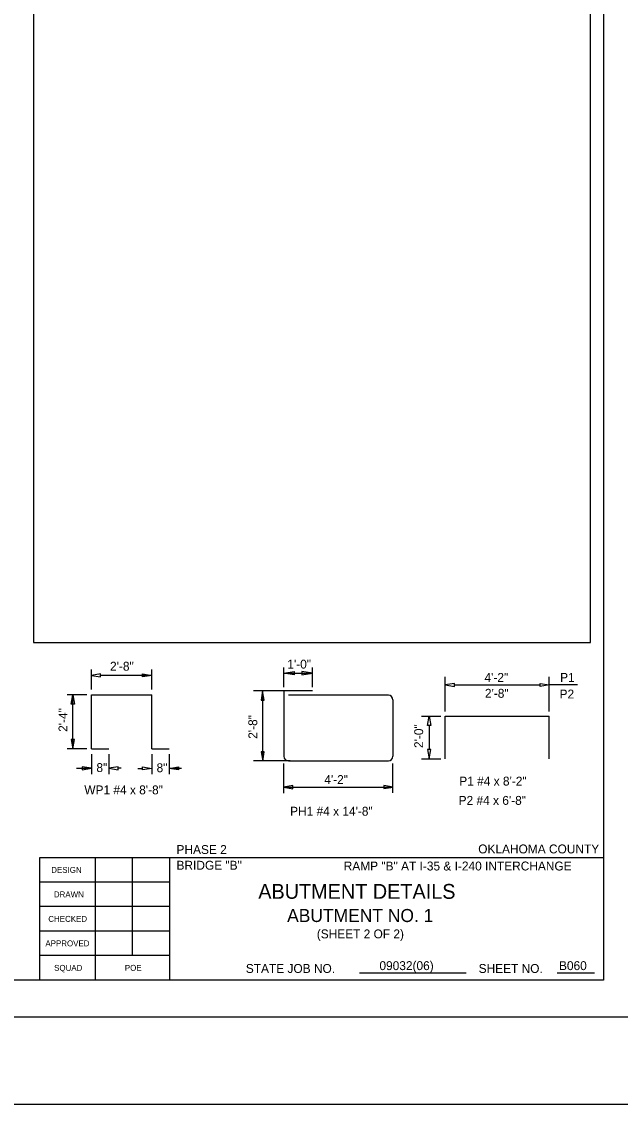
# Model space of a CAD drawing. Extents: x 2146724 to 2153191, y 139029 to 143935.
# Drawn here: x 2147223.9 to 2147256.2, y 143589.8 to 143648.2 of the extents above; entities that cross this region are included whole.
import ezdxf

# ---------------------------------------------------------------- set-up
doc = ezdxf.new("R2010")
doc.units = 0
for name, color, linetype in [('Default', 7, 'Continuous'), ('PR_Bridge_Rebar', 7, 'Continuous'), ('PR_Dimensions', 7, 'Continuous'), ('SHT_Plot_Shape_Full', 7, 'Continuous'), ('SHT_Plot_Shape_Half', 7, 'Continuous'), ('SHT_Sheet_Border', 7, 'Continuous'), ('SHT_Standard_Sheet_Lines', 7, 'Continuous'), ('SHT_Standard_Sheet_Txt', 7, 'Continuous'), ('T', 7, 'Continuous'), ('T-Subtitle', 7, 'Continuous'), ('T-Title', 7, 'Continuous')]:
    doc.layers.add(name, color=color, linetype=linetype)

# ---------------------------------------------------------------- blocks, each defined once
blk = doc.blocks.new('ARROWHD_11')
at = {"layer": 'Default'}
blk.add_lwpolyline([(0.0261, -0.0045), (0.0261, 0.0043), (-0.0004, -0.0001)], close=True, dxfattribs=at)

msp = doc.modelspace()

# ---------------------------------------------------------------- linework, layer by layer
at = {"layer": 'PR_Bridge_Rebar'}
for p, q in [((2147227.664, 143611.849), (2147230.921, 143611.849)), ((2147227.664, 143608.951), (2147227.664, 143611.849)), ((2147230.921, 143608.951), (2147230.921, 143611.849)), ((2147238.049, 143612.068), (2147238.049, 143608.543)), ((2147239.588, 143612.068), (2147238.049, 143612.068)), ((2147243.687, 143611.833), (2147238.299, 143611.833)), ((2147243.937, 143611.583), (2147243.937, 143608.543)), ((2147246.749, 143610.708), (2147252.37, 143610.708)), ((2147246.749, 143608.411), (2147246.749, 143610.708)), ((2147252.37, 143608.411), (2147252.37, 143610.708)), ((2147227.664, 143608.951), (2147228.606, 143608.951)), ((2147230.921, 143608.951), (2147231.863, 143608.951)), ((2147238.299, 143608.293), (2147243.687, 143608.293))]:
    msp.add_line(p, q, dxfattribs=at)
for centre, start, end in [((2147243.687, 143611.583), 0, 90), ((2147238.299, 143608.543), 180, 270), ((2147243.687, 143608.543), 270, 0)]:
    msp.add_arc(centre, 0.25, start, end, dxfattribs=at)
at = {"layer": 'PR_Dimensions'}
for p, q in [((2147227.664, 143612.141), (2147227.664, 143613.22)), ((2147230.921, 143612.906), (2147228.164, 143612.906)), ((2147230.921, 143612.141), (2147230.921, 143613.22)), ((2147238.049, 143612.266), (2147238.049, 143613.323)), ((2147238.049, 143613.024), (2147239.588, 143613.024)), ((2147239.588, 143612.266), (2147239.588, 143613.323)), ((2147246.749, 143610.958), (2147246.749, 143612.836)), ((2147252.37, 143610.958), (2147252.37, 143612.836)), ((2147247.249, 143612.39), (2147251.87, 143612.39)), ((2147253.892, 143612.39), (2147252.37, 143612.39)), ((2147227.414, 143611.849), (2147226.354, 143611.849)), ((2147226.665, 143608.951), (2147226.665, 143611.849)), ((2147238.412, 143612.068), (2147236.417, 143612.068)), ((2147236.906, 143612.068), (2147236.906, 143608.293)), ((2147245.478, 143610.708), (2147246.513, 143610.708)), ((2147245.892, 143610.208), (2147245.892, 143608.911)), ((2147227.414, 143608.951), (2147226.354, 143608.951)), ((2147227.664, 143608.658), (2147227.664, 143607.583)), ((2147228.606, 143608.658), (2147228.606, 143607.583)), ((2147230.921, 143608.658), (2147230.921, 143607.576)), ((2147231.863, 143608.658), (2147231.863, 143607.576)), ((2147238.381, 143608.293), (2147236.417, 143608.293)), ((2147245.478, 143608.411), (2147246.513, 143608.411)), ((2147226.868, 143607.897), (2147227.664, 143607.897)), ((2147229.276, 143607.897), (2147229.106, 143607.897)), ((2147230.169, 143607.889), (2147230.421, 143607.889)), ((2147232.527, 143607.889), (2147231.863, 143607.889)), ((2147238.049, 143606.56), (2147238.049, 143608.16)), ((2147243.937, 143606.569), (2147243.937, 143608.16)), ((2147238.049, 143606.883), (2147243.937, 143606.883))]:
    msp.add_line(p, q, dxfattribs=at)
for points in [[(2147224.535, 143614.674), (2147254.586, 143614.674), (2147254.586, 143656.446), (2147224.535, 143656.446)], [(2147228.164, 143612.823), (2147228.164, 143612.99), (2147227.664, 143612.906)], [(2147230.421, 143612.823), (2147230.421, 143612.99), (2147230.921, 143612.906)], [(2147238.609, 143612.931), (2147238.049, 143613.024), (2147238.609, 143613.117)], [(2147239.028, 143612.931), (2147239.588, 143613.024), (2147239.028, 143613.117)], [(2147247.249, 143612.306), (2147247.249, 143612.473), (2147246.749, 143612.39)], [(2147251.87, 143612.306), (2147251.87, 143612.473), (2147252.37, 143612.39)], [(2147226.749, 143611.349), (2147226.582, 143611.349), (2147226.665, 143611.849)], [(2147245.975, 143610.208), (2147245.808, 143610.208), (2147245.892, 143610.708)], [(2147226.747, 143609.444), (2147226.58, 143609.444), (2147226.664, 143608.944)], [(2147245.975, 143608.911), (2147245.808, 143608.911), (2147245.892, 143608.411)], [(2147227.164, 143607.98), (2147227.164, 143607.814), (2147227.664, 143607.897)], [(2147229.106, 143607.814), (2147229.106, 143607.98), (2147228.606, 143607.897)], [(2147230.421, 143607.806), (2147230.421, 143607.973), (2147230.921, 143607.889)], [(2147232.363, 143607.973), (2147232.363, 143607.806), (2147231.863, 143607.889)]]:
    msp.add_lwpolyline(points, close=True, dxfattribs=at)
at = {"layer": 'SHT_Plot_Shape_Full'}
msp.add_lwpolyline([(2147114.94, 143685.779), (2147258.94, 143685.779), (2147258.94, 143589.779), (2147114.94, 143589.779)], close=True, dxfattribs=at)
at = {"layer": 'SHT_Plot_Shape_Half'}
msp.add_lwpolyline([(2147121.49, 143682.479), (2147257.49, 143682.479), (2147257.49, 143594.479), (2147121.49, 143594.479)], close=True, dxfattribs=at)
at = {"layer": 'SHT_Sheet_Border'}
for p, q in [((2147224.89, 143596.479), (2147224.89, 143603.079)), ((2147224.89, 143603.079), (2147255.29, 143603.079)), ((2147231.889, 143596.479), (2147231.889, 143603.082)), ((2147231.889, 143596.479), (2147231.889, 143603.082))]:
    msp.add_line(p, q, dxfattribs=at)
msp.add_lwpolyline([(2147255.29, 143596.479), (2147129.29, 143596.479), (2147129.29, 143680.479), (2147255.29, 143680.479)], close=True, dxfattribs=at)
at = {"layer": 'SHT_Standard_Sheet_Lines'}
for p, q in [((2147227.889, 143596.479), (2147227.889, 143603.082)), ((2147229.889, 143597.8), (2147229.889, 143603.082)), ((2147242.132, 143596.864), (2147247.894, 143596.864)), ((2147242.132, 143596.864), (2147247.894, 143596.864)), ((2147252.791, 143596.864), (2147254.801, 143596.864)), ((2147252.791, 143596.864), (2147254.801, 143596.864))]:
    msp.add_line(p, q, dxfattribs=at)
for points in [[(2147231.889, 143601.759), (2147224.89, 143601.759)], [(2147231.889, 143600.439), (2147224.89, 143600.439)], [(2147231.889, 143599.119), (2147224.89, 143599.119)], [(2147231.889, 143597.799), (2147224.89, 143597.799)]]:
    msp.add_lwpolyline(points, dxfattribs=at)

# ---------------------------------------------------------------- block references
at = {"layer": 'PR_Dimensions', "xscale": 18.897599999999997, "yscale": 18.897599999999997}
for p, rotation in [((2147236.906, 143612.068), -90.00000000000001), ((2147236.906, 143608.293), 89.99999999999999), ((2147243.937, 143606.883), 180)]:
    msp.add_blockref('ARROWHD_11', p, dxfattribs=dict(at, rotation=rotation))
msp.add_blockref('ARROWHD_11', (2147238.049, 143606.883), dxfattribs=at)

# ---------------------------------------------------------------- texts
at = {"layer": 'SHT_Standard_Sheet_Txt'}
for s, height, p in [('DESIGN', 0.32, (2147225.498, 143602.259)), ('DRAWN', 0.32, (2147225.641, 143600.938)), ('CHECKED', 0.32, (2147225.341, 143599.618)), ('APPROVED', 0.32, (2147225.184, 143598.297)), ('SQUAD', 0.32, (2147225.655, 143596.976)), ('POE', 0.32, (2147229.47, 143596.979)), ('STATE JOB NO.', 0.48, (2147235.998, 143596.864)), ('STATE JOB NO.', 0.48, (2147235.998, 143596.864)), ('SHEET NO. ', 0.48, (2147248.558, 143596.864)), ('SHEET NO. ', 0.48, (2147248.559, 143596.864))]:
    msp.add_text(s, height=height, dxfattribs=at).set_placement(p)
at = {"layer": 'T'}
for s, height, p in [('2\'-8"', 0.48, (2147228.672, 143613.159)), ('1\'-0"', 0.48, (2147238.238, 143613.273)), ('4\'-2"', 0.48, (2147248.877, 143612.557)), ('P1', 0.48, (2147252.955, 143612.557)), ('2\'-8"', 0.48, (2147248.898, 143611.699)), ('P2', 0.48, (2147252.924, 143611.66)), ('8"', 0.48, (2147227.937, 143607.694)), ('8"', 0.48, (2147231.183, 143607.686)), ('4\'-2"', 0.48, (2147240.231, 143607.048)), ('P1 #4 x 8\'-2"', 0.48, (2147247.514, 143606.965)), ('WP1 #4 x 8\'-8"', 0.48, (2147227.284, 143606.492)), ('P2 #4 x 6\'-8"', 0.48, (2147247.48, 143605.926)), ('PH1 #4 x 14\'-8"', 0.48, (2147238.388, 143605.342)), ('PHASE 2', 0.48, (2147232.258, 143603.276)), ('OKLAHOMA COUNTY', 0.48, (2147248.537, 143603.308)), ('BRIDGE "B"', 0.48, (2147232.258, 143602.429)), ('RAMP "B" AT I-35 & I-240 INTERCHANGE', 0.48, (2147241.279, 143602.388)), ('(SHEET 2 OF 2)', 0.47917, (2147239.829, 143598.728)), ('09032(06)', 0.48, (2147243.207, 143597.016)), ('B060', 0.48, (2147252.894, 143597.016))]:
    msp.add_text(s, height=height, dxfattribs=at).set_placement(p)
for s, p in [('2\'-4"', (2147226.373, 143609.861)), ('2\'-8"', (2147236.615, 143609.487)), ('2\'-0"', (2147245.565, 143608.99))]:
    msp.add_text(s, height=0.48, rotation=90, dxfattribs=at).set_placement(p)
at = {"layer": 'T-Subtitle'}
msp.add_text('ABUTMENT NO. 1', height=0.70312, dxfattribs=at).set_placement((2147238.226, 143599.608))
at = {"layer": 'T-Title'}
msp.add_text('ABUTMENT DETAILS', height=0.79999, dxfattribs=at).set_placement((2147236.669, 143600.86))

doc.saveas('drawing.dxf')
